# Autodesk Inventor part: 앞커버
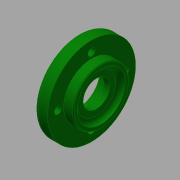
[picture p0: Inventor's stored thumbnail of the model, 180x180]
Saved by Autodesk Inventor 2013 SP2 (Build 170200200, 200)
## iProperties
Created: 2015-12
Part Number: 앞커버
Material: 일반
Document SubType Name: Modeling
Designer: mduedu
Density: 1 g/cm^3
Author: mduedu
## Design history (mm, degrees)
sketch "스케치1"
  geometry: L1 (0, 0)-(14, 0); L2 (14, 0)-(14, 17.5); L3 (14, 17.5)-(8, 17.5); L4 (8, 17.5)-(8, 27.5); L5 (8, 27.5)-(0, 27.5); L6 (0, 27.5)-(0, 0)
  constraints: 12 end point, 4 parallel, 1 horizontal, 1 perpendicular
  dimensions: "d0" = 14 distance between parallel lines of L2 L6; "d2" = 8 distance of L4.end L5.end; "d3" = 55 diameter of L5 L1; "d4" = 35 diameter of L3 L1
revolve "회전1" sketch "스케치1" stored, may be unused: angle "d5" = 90 deg
hole "구멍1" diameter "d8" = 30; stored, may be unused: countersink angle "d12" = 90 deg, drill point angle "d14" = 0 deg; dims "d6" = 10, "d7" = 10, "d9" = 6, "d10" = 4, "d11" = 2, "d13" = 3
hole "구멍2" diameter "d17" = 25; stored, may be unused: countersink angle "d21" = 90 deg, drill point angle "d23" = 0 deg; dims "d15" = 10, "d16" = 10, "d18" = 6, "d19" = 4, "d20" = 2, "d22" = 7.3
hole "구멍3" diameter "d26" = 16.5; stored, may be unused: countersink angle "d30" = 90 deg, drill point angle "d32" = 0 deg; dims "d24" = 10, "d25" = 10, "d27" = 6, "d28" = 4, "d29" = 2, "d31" = 7.3
fillet "모깎기1" dims "d33" = 0.3
chamfer "모따기1" distance "d34" = 1; stored, may be unused: second distance "d35" = 2, angle "d36" = 30 deg
fillet "모깎기2" dims "d37" = 3
fillet "모깎기3" dims "d38" = 2
chamfer "모따기2" distance "d39" = 0.5; stored, may be unused: second distance "d40" = 2, angle "d41" = 45 deg
sketch "스케치2" dims "d42" = 42
  geometry: 9 further points
  constraints: 3 coincident, 2 vertical alignment, 9 other
  dimensions: "d46" = 360 deg dimension on point (0, 0) point (0, 21) (derived)
sketch "스케치3"
  geometry: 4 further points
hole "구멍4" sketch "스케치3" at (-21, 0), (0, -21), (21, 0), (0, 21) diameter "d50" = 4.5; stored, may be unused: countersink angle "d54" = 90 deg, drill point angle "d56" = 0 deg; dims "d51" = 6, "d52" = 8, "d53" = 4.6, "d55" = 8
node "솔리드1"
